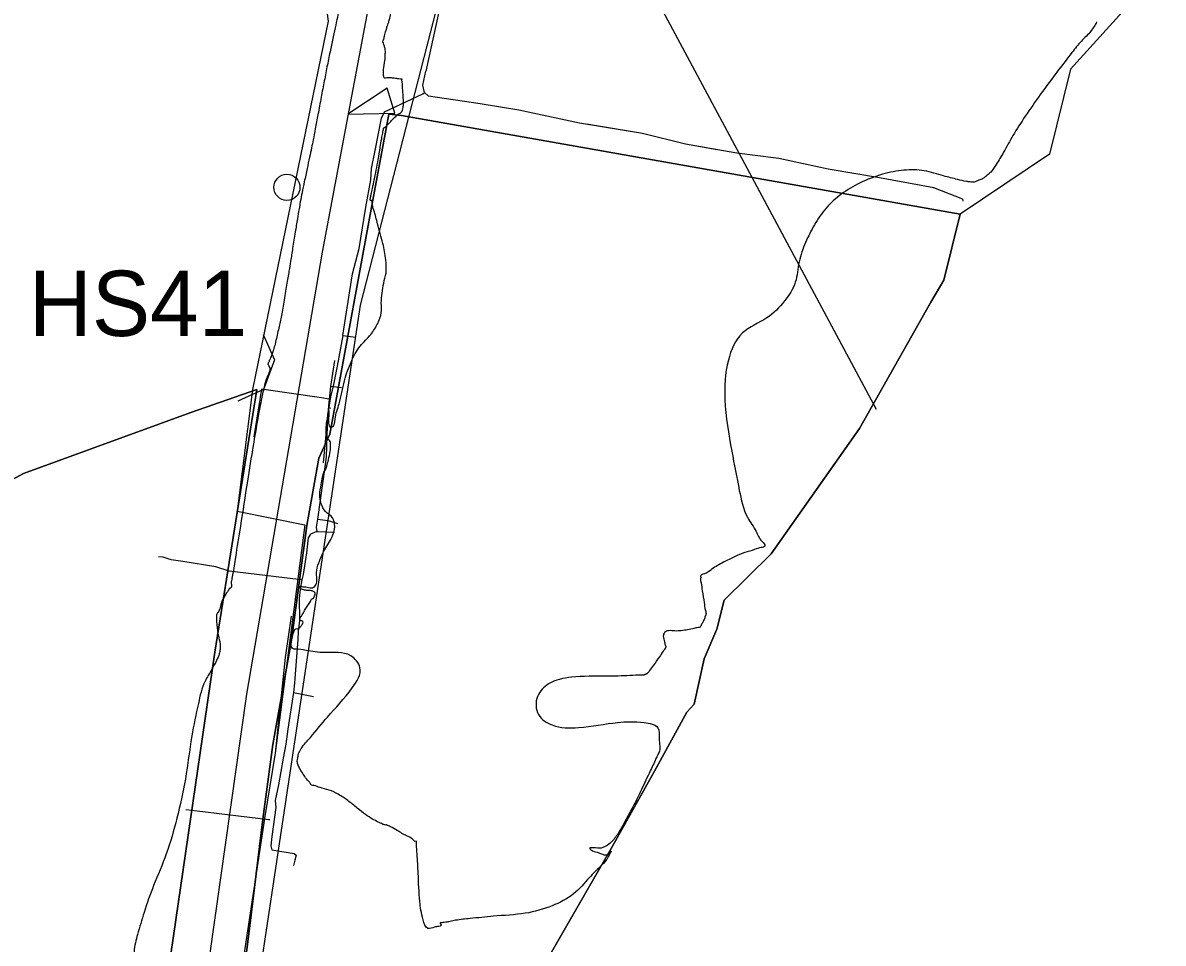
# Model space of a CAD drawing. Extents: x -478645 to -472650, y -1118147 to -1113892.
# Drawn here: x -475972.9 to -475798.3, y -1117585.1 to -1117444.2 of the extents above; entities that cross this region are included whole.
import ezdxf

# ---------------------------------------------------------------- set-up
doc = ezdxf.new("R2010")
doc.units = 0
for name, color, linetype in [('cesty', 7, 'Continuous'), ('el vedeni _VN', 7, 'Continuous'), ('hospodářské sjezdy', 7, 'Continuous'), ('ObPÚ', 7, 'Continuous'), ('plyn_stl', 7, 'Continuous'), ('silnice', 7, 'Continuous'), ('telekomunikační kabel_O2', 7, 'Continuous'), ('VAK_vodovod', 7, 'Continuous'), ('Vrstevnice_vedlejsi', 7, 'Continuous')]:
    doc.layers.add(name, color=color, linetype=linetype)

msp = doc.modelspace()

# ---------------------------------------------------------------- linework, layer by layer
at = {"layer": 'cesty'}
msp.add_line((-475915.938, -1117457.98), (-475917.133, -1117454.162), dxfattribs=at)
msp.add_lwpolyline([(-475917.133, -1117454.162), (-475923.164, -1117458.147), (-475915.938, -1117457.98)], dxfattribs=at)
msp.add_circle((-475932.467, -1117469.362), 2, dxfattribs=at)
at = {"layer": 'el vedeni _VN'}
msp.add_lwpolyline([(-475915.707, -1117366.222), (-475842.25, -1117503.35)], dxfattribs=at)
at = {"layer": 'hospodářské sjezdy'}
for p, q in [((-475936.094, -1117491.874), (-475934.346, -1117495.765)), ((-475934.346, -1117495.765), (-475936.078, -1117500.333)), ((-475936.078, -1117500.333), (-475939.967, -1117502.085))]:
    msp.add_line(p, q, dxfattribs=at)
at = {"layer": 'ObPÚ'}
for p, q in [((-475916.88, -1117458.16), (-475919.49, -1117472.13)), ((-475919.49, -1117472.13), (-475925.88, -1117507.14)), ((-475934.6, -1117554.69), (-475936.13, -1117566.09))]:
    msp.add_line(p, q, dxfattribs=at)
for points in [[(-475797.1, -1117434.24), (-475812.51, -1117451.24), (-475815.72, -1117464.29), (-475829.4, -1117473.48), (-475914.94, -1117458.35), (-475916.88, -1117458.16), (-475919.49, -1117472.13), (-475925.88, -1117507.14), (-475927.57, -1117510.84), (-475929.43, -1117521.14), (-475931.78, -1117538.72), (-475934.6, -1117554.69), (-475936.13, -1117566.09), (-475938.19, -1117582.83), (-475940.34, -1117599.73)], [(-475951.7, -1117685.1), (-475927.26, -1117688.72), (-475918.95, -1117689.8), (-475884.78, -1117695.44), (-475871.68, -1117697.52), (-475898.5, -1117669.12), (-475903.93, -1117664.35), (-475905.71, -1117629.13), (-475906.78, -1117612.16), (-475902.49, -1117604.75), (-475882.63, -1117570.25), (-475876.2, -1117558.77), (-475871.25, -1117549.71), (-475870.12, -1117548.49), (-475868.56, -1117541.56), (-475866.64, -1117537.01), (-475865.5, -1117532.56), (-475858.35, -1117525.46), (-475844.8, -1117506.28), (-475833.86, -1117486.94), (-475831.88, -1117483.59), (-475829.4, -1117473.48), (-475914.94, -1117458.35), (-475916.88, -1117458.16)], [(-475919.49, -1117472.13), (-475916.88, -1117458.16), (-475914.94, -1117458.35), (-475829.4, -1117473.48), (-475831.88, -1117483.59), (-475833.86, -1117486.94), (-475844.8, -1117506.28), (-475858.35, -1117525.46), (-475865.5, -1117532.56), (-475866.64, -1117537.01), (-475868.56, -1117541.56), (-475870.12, -1117548.49), (-475871.25, -1117549.71), (-475876.2, -1117558.77), (-475882.63, -1117570.25), (-475902.49, -1117604.75)], [(-475940.34, -1117599.73), (-475938.19, -1117582.83), (-475936.13, -1117566.09), (-475934.6, -1117554.69), (-475931.78, -1117538.72), (-475929.43, -1117521.14), (-475927.57, -1117510.84), (-475925.88, -1117507.14), (-475919.49, -1117472.13)], [(-475937.08, -1117500.29), (-475943.5, -1117540.53), (-475950.59, -1117589.22), (-475972.84, -1117590.29), (-476004.64, -1117592.26), (-475999.55, -1117575.26), (-475994.23, -1117573.44), (-475992.2, -1117563.25), (-475986.19, -1117534.11), (-475984.93, -1117525.82), (-475982.04, -1117518.19), (-475972.81, -1117513.2), (-475947.17, -1117503.84), (-475937.08, -1117500.29)], [(-475947.17, -1117503.84), (-475972.81, -1117513.2), (-475982.04, -1117518.19), (-475984.93, -1117525.82), (-475986.19, -1117534.11), (-475992.2, -1117563.25), (-475994.23, -1117573.44), (-475999.55, -1117575.26), (-476004.64, -1117592.26), (-475972.84, -1117590.29), (-475950.59, -1117589.22), (-475943.5, -1117540.53), (-475937.08, -1117500.29), (-475947.17, -1117503.84)], [(-475925.88, -1117507.14), (-475927.57, -1117510.84), (-475929.43, -1117521.14), (-475931.78, -1117538.72), (-475934.6, -1117554.69)], [(-475936.13, -1117566.09), (-475938.19, -1117582.83), (-475940.34, -1117599.73)]]:
    msp.add_lwpolyline(points, dxfattribs=at)
at = {"layer": 'plyn_stl'}
for p, q in [((-475925.98, -1117501.775), (-475926.943, -1117511.519)), ((-475947.94, -1117564.611), (-475946.213, -1117564.822)), ((-475946.213, -1117564.822), (-475935.234, -1117566.161)), ((-475935.234, -1117566.161), (-475935.062, -1117566.182))]:
    msp.add_line(p, q, dxfattribs=at)
for points in [[(-475925.179, -1117495.887), (-475925.776, -1117499.864), (-475925.98, -1117501.775), (-475927.156, -1117501.607), (-475936.338, -1117500.287), (-475937.535, -1117507.551)], [(-475924.115, -1117500.041), (-475924.12, -1117500.04), (-475924.5, -1117500), (-475925.776, -1117499.864)]]:
    msp.add_lwpolyline(points, dxfattribs=at)
at = {"layer": 'silnice'}
msp.add_lwpolyline([(-475957.898, -1117684.778), (-475949.882, -1117626.621), (-475938.626, -1117546.976), (-475927.029, -1117479.269), (-475917.649, -1117429.299), (-475903.982, -1117378.322)], dxfattribs=at)
at = {"layer": 'telekomunikační kabel_O2'}
for points in [[(-475967.4, -1117098.97), (-475940.43, -1117167.78), (-475950.06, -1117174), (-475931.33, -1117228.82), (-475924.1, -1117281.32), (-475911.23, -1117358.65), (-475927.92, -1117430.83), (-475926.17, -1117443.9), (-475937.75, -1117500.32), (-475940.1, -1117518.94), (-475929.72, -1117521.06), (-475934.27, -1117556.02), (-475935.89, -1117566.02), (-475936.969, -1117573.032)], [(-475891.45, -1117356.54), (-475891.64, -1117357.2), (-475890.45, -1117362.41), (-475889.23, -1117368.48), (-475890.21, -1117370.93), (-475900.63, -1117410.24), (-475907.44, -1117434.27), (-475911.21, -1117451.58)], [(-475911.41, -1117454.83), (-475911.67, -1117453.71), (-475911.21, -1117451.58)], [(-475923.91, -1117492.02), (-475922.43, -1117482.59), (-475921.39, -1117478.74), (-475920.39, -1117472.37), (-475919.64, -1117468.22), (-475919.5, -1117466.47), (-475918.95, -1117463.72), (-475918, -1117458.79), (-475917.51, -1117457.78), (-475911.68, -1117455.04), (-475911.41, -1117454.83)], [(-475866.596, -1117463.609), (-475871.46, -1117462.74), (-475878.05, -1117461.1), (-475887.67, -1117459.53), (-475896.96, -1117457.53), (-475902.86, -1117456.57), (-475910.78, -1117455.39), (-475911.41, -1117454.83)], [(-475857.14, -1117464.96), (-475863.57, -1117464.15), (-475871.46, -1117462.74), (-475878.05, -1117461.1), (-475886.596, -1117459.705)], [(-475828.923, -1117471.474), (-475828.99, -1117471.15), (-475833.42, -1117469.44), (-475841.75, -1117467.88), (-475849.62, -1117466.56), (-475857.14, -1117464.96)], [(-475923.91, -1117492.02), (-475924.79, -1117496.76), (-475925.31, -1117499.54), (-475925.81, -1117501.42), (-475926.04, -1117503.08)], [(-475923.91, -1117492.02), (-475921.9, -1117492.32)], [(-475926.04, -1117503.08), (-475926.26, -1117504.12), (-475926.26, -1117504.92), (-475926.36, -1117507.25), (-475926.48, -1117510.66), (-475926.65, -1117512.14), (-475927.78, -1117520.16)], [(-475926.04, -1117503.08), (-475925.78, -1117503.17)], [(-475927.78, -1117520.16), (-475927.97, -1117521.4), (-475927.89, -1117522.04)], [(-475927.78, -1117520.16), (-475926.14, -1117520.38), (-475924.73, -1117520.81)], [(-475927.89, -1117522.04), (-475928.86, -1117522.49), (-475929.19, -1117523.03), (-475929.45, -1117525.32), (-475929.97, -1117528.65), (-475930.16, -1117529.45)], [(-475927.89, -1117522.04), (-475925.19, -1117522.16)], [(-475930.16, -1117529.45), (-475931.57, -1117529.33), (-475941.31, -1117528.12), (-475943.33, -1117527.48), (-475948.39, -1117526.66), (-475950.2, -1117526.42), (-475951.4, -1117525.97), (-475952.12, -1117525.92)], [(-475930.16, -1117529.45), (-475930.43, -1117530.9), (-475930.6, -1117532.33), (-475930.55, -1117535.71), (-475930.75, -1117537.38), (-475930.78, -1117538.62), (-475931.26, -1117544.56), (-475931.29, -1117545.26), (-475931.44, -1117546.73)], [(-475931.82, -1117535.04), (-475932.74, -1117541.33), (-475934.27, -1117556.02), (-475935.89, -1117566.02), (-475937.71, -1117577.81), (-475938.91, -1117585.91), (-475941.61, -1117604.26), (-475944.33, -1117624.51)], [(-475931.44, -1117546.73), (-475932.33, -1117552.33), (-475932.65, -1117554.6), (-475933.06, -1117556.79), (-475933.78, -1117560.85), (-475934.28, -1117563.23), (-475934.17, -1117564.33), (-475934.76, -1117568.78), (-475934.91, -1117570.19), (-475934.8, -1117570.81), (-475931.38, -1117571.38), (-475931.07, -1117571.61), (-475931.27, -1117572.4), (-475931.48, -1117573.22)], [(-475931.44, -1117546.73), (-475928.4, -1117547.31)]]:
    msp.add_lwpolyline(points, dxfattribs=at)
at = {"layer": 'VAK_vodovod'}
msp.add_lwpolyline([(-475961.022, -1117076.006), (-475947.88, -1117107.78), (-475947.26, -1117108.989), (-475886.863, -1117255.251), (-475879.338, -1117287.714), (-475878.218, -1117296.341), (-475877.862, -1117316.562), (-475878.829, -1117320.819), (-475879.236, -1117324.31), (-475879.403, -1117324.54), (-475921.268, -1117487.378), (-475934.347, -1117574.649), (-475937.667, -1117596.666), (-475938.465, -1117600.746), (-475938.582, -1117601.233), (-475938.757, -1117601.897), (-475940.979, -1117601.583)], dxfattribs=at)
at = {"layer": 'Vrstevnice_vedlejsi'}
for points in [[(-475916.975, -1117444.292), (-475916.91, -1117444.15), (-475916.838, -1117443.929), (-475916.758, -1117443.629), (-475916.67, -1117443.25), (-475916.443, -1117442.153), (-475916.077, -1117440.337), (-475915.571, -1117437.802), (-475915.215, -1117436.045), (-475915.01, -1117435.066), (-475914.956, -1117434.864), (-475914.76, -1117434.04), (-475914.422, -1117432.594), (-475913.943, -1117430.524), (-475913.61, -1117429.082), (-475913.424, -1117428.266), (-475913.385, -1117428.077), (-475913.184, -1117427.193), (-475912.819, -1117425.614), (-475912.291, -1117423.339), (-475911.931, -1117421.787), (-475911.737, -1117420.958), (-475911.711, -1117420.852), (-475911.47, -1117419.881), (-475911.014, -1117418.045), (-475910.343, -1117415.344), (-475909.896, -1117413.541), (-475909.671, -1117412.636), (-475909.669, -1117412.628), (-475909.667, -1117412.619), (-475909.664, -1117412.607), (-475909.661, -1117412.594), (-475909.477, -1117411.965), (-475909.111, -1117410.721), (-475908.564, -1117408.862), (-475908.198, -1117407.614), (-475908.011, -1117406.977), (-475908.005, -1117406.952), (-475908, -1117406.932), (-475907.996, -1117406.917), (-475907.995, -1117406.907), (-475907.754, -1117405.931), (-475907.275, -1117403.988), (-475906.557, -1117401.079), (-475905.997, -1117398.788), (-475905.596, -1117397.117), (-475905.352, -1117396.064), (-475905.125, -1117395.027), (-475904.914, -1117394.006), (-475904.721, -1117393.002), (-475904.431, -1117391.559), (-475904.045, -1117389.677), (-475903.563, -1117387.357), (-475903.25, -1117385.773), (-475903.106, -1117384.926), (-475903.131, -1117384.815), (-475903.261, -1117384.756), (-475903.497, -1117384.749), (-475903.839, -1117384.794), (-475904.936, -1117385.955), (-475906.789, -1117388.231), (-475909.397, -1117391.622), (-475911.147, -1117393.894), (-475912.039, -1117395.047), (-475912.072, -1117395.08), (-475912.108, -1117395.141), (-475912.145, -1117395.227), (-475912.185, -1117395.34), (-475912.276, -1117395.491), (-475912.417, -1117395.68), (-475912.611, -1117395.908), (-475913.012, -1117397.232), (-475913.622, -1117399.653), (-475914.441, -1117403.172), (-475915.248, -1117406.458), (-475916.043, -1117409.512), (-475916.828, -1117412.333), (-475917.46, -1117414.614), (-475917.94, -1117416.353), (-475918.268, -1117417.552), (-475918.666, -1117419.012), (-475919.134, -1117420.732), (-475919.673, -1117422.713), (-475920.196, -1117424.706), (-475920.704, -1117426.711), (-475921.195, -1117428.727), (-475921.645, -1117430.593), (-475922.054, -1117432.306), (-475922.421, -1117433.869), (-475922.836, -1117435.571), (-475923.299, -1117437.415), (-475923.809, -1117439.399), (-475924.263, -1117441.241), (-475924.661, -1117442.942), (-475925.002, -1117444.501), (-475925.384, -1117446.3), (-475925.807, -1117448.34)], [(-475926.806, -1117512.989), (-475926.594, -1117512.679), (-475926.364, -1117512.04), (-475926.115, -1117511.073), (-475925.848, -1117509.779), (-475925.79, -1117508.798), (-475925.942, -1117508.13), (-475926.304, -1117507.777), (-475926.467, -1117507.007), (-475926.43, -1117505.822), (-475926.193, -1117504.22), (-475926.061, -1117503.535), (-475926.032, -1117503.767), (-475926.107, -1117504.915), (-475926.054, -1117505.677), (-475925.872, -1117506.054), (-475925.562, -1117506.044), (-475925.091, -1117504.861), (-475924.459, -1117502.506), (-475923.667, -1117498.977), (-475922.599, -1117496.031), (-475921.256, -1117493.667), (-475919.639, -1117491.885), (-475918.56, -1117490.191), (-475918.018, -1117488.587), (-475918.015, -1117487.071), (-475917.893, -1117485.547), (-475917.653, -1117484.016), (-475917.295, -1117482.477), (-475917.333, -1117480.451), (-475917.767, -1117477.938), (-475918.596, -1117474.938), (-475919.15, -1117472.871), (-475919.428, -1117471.736), (-475919.431, -1117471.534), (-475919.47, -1117471.408), (-475919.543, -1117471.356), (-475919.652, -1117471.379), (-475919.714, -1117471.331), (-475919.728, -1117471.212), (-475919.695, -1117471.021), (-475919.578, -1117470.457), (-475919.377, -1117469.521), (-475919.091, -1117468.211), (-475918.797, -1117466.73), (-475918.495, -1117465.079), (-475918.184, -1117463.257), (-475917.954, -1117461.912), (-475917.804, -1117461.044), (-475917.736, -1117460.653), (-475917.673, -1117460.385), (-475917.615, -1117460.241), (-475917.563, -1117460.221), (-475917.503, -1117460.188), (-475917.434, -1117460.142), (-475917.357, -1117460.084), (-475917.117, -1117459.844), (-475916.715, -1117459.423), (-475916.15, -1117458.821), (-475915.694, -1117458.384), (-475915.347, -1117458.112), (-475915.11, -1117458.006), (-475914.917, -1117457.811), (-475914.77, -1117457.525), (-475914.668, -1117457.15), (-475914.632, -1117456.464), (-475914.662, -1117455.467), (-475914.757, -1117454.161), (-475914.82, -1117453.286), (-475914.849, -1117452.843), (-475914.845, -1117452.831), (-475914.844, -1117452.821), (-475914.845, -1117452.811), (-475914.848, -1117452.803), (-475914.854, -1117452.799), (-475914.862, -1117452.799), (-475914.872, -1117452.802), (-475915.096, -1117452.775), (-475915.535, -1117452.719), (-475916.188, -1117452.632), (-475916.735, -1117452.594), (-475917.175, -1117452.603), (-475917.509, -1117452.66), (-475917.671, -1117452.239), (-475917.659, -1117451.338), (-475917.476, -1117449.959), (-475917.402, -1117448.881), (-475917.44, -1117448.105), (-475917.587, -1117447.631), (-475917.691, -1117447.306), (-475917.752, -1117447.131), (-475917.769, -1117447.105), (-475917.697, -1117446.794), (-475917.537, -1117446.198), (-475917.288, -1117445.316), (-475917.101, -1117444.68), (-475916.975, -1117444.292)], [(-475808.497, -1117444.035), (-475808.88, -1117444.729), (-475809.396, -1117445.448), (-475810.046, -1117446.192), (-475810.829, -1117446.96), (-475812.268, -1117448.71), (-475814.364, -1117451.44), (-475817.116, -1117455.152), (-475819.429, -1117458.48), (-475821.301, -1117461.425), (-475822.733, -1117463.986), (-475823.869, -1117465.856), (-475824.71, -1117467.033), (-475825.256, -1117467.518), (-475825.714, -1117467.878), (-475826.086, -1117468.115), (-475826.372, -1117468.227), (-475826.636, -1117468.331), (-475826.88, -1117468.427), (-475827.102, -1117468.514), (-475827.434, -1117468.549), (-475827.875, -1117468.533), (-475828.425, -1117468.465), (-475829.777, -1117468.158), (-475831.929, -1117467.611), (-475834.883, -1117466.824), (-475837.998, -1117466.742), (-475841.274, -1117467.362), (-475844.71, -1117468.687), (-475847.59, -1117470.415), (-475849.915, -1117472.545), (-475851.683, -1117475.078), (-475853.059, -1117477.814), (-475854.041, -1117480.752), (-475854.63, -1117483.892), (-475856.275, -1117486.757), (-475858.974, -1117489.346), (-475862.729, -1117491.66), (-475864.878, -1117495.835), (-475865.419, -1117501.869), (-475864.354, -1117509.765), (-475863.199, -1117515.764), (-475861.956, -1117519.867), (-475860.624, -1117522.073), (-475859.743, -1117523.554), (-475859.312, -1117524.308), (-475859.332, -1117524.337), (-475859.846, -1117524.509), (-475860.853, -1117524.824), (-475862.354, -1117525.281), (-475863.943, -1117525.933), (-475865.62, -1117526.779), (-475867.386, -1117527.82), (-475868.557, -1117528.532), (-475869.131, -1117528.918), (-475869.11, -1117528.976), (-475869.104, -1117529.054), (-475869.115, -1117529.153), (-475869.141, -1117529.272), (-475869.061, -1117529.943), (-475868.875, -1117531.166), (-475868.582, -1117532.941), (-475868.393, -1117534.142), (-475868.307, -1117534.77), (-475868.324, -1117534.824), (-475868.346, -1117534.875), (-475868.373, -1117534.923), (-475868.404, -1117534.968), (-475868.435, -1117535.044), (-475868.464, -1117535.15), (-475868.491, -1117535.288), (-475868.585, -1117535.521), (-475868.744, -1117535.849), (-475868.969, -1117536.272), (-475869.119, -1117536.555), (-475869.195, -1117536.699), (-475869.197, -1117536.704), (-475869.518, -1117536.776), (-475870.159, -1117536.915), (-475871.12, -1117537.121), (-475872.088, -1117537.246), (-475873.063, -1117537.289), (-475874.046, -1117537.25), (-475874.637, -1117537.514), (-475874.836, -1117538.082), (-475874.643, -1117538.952), (-475874.526, -1117539.55), (-475874.485, -1117539.876), (-475874.521, -1117539.93), (-475874.841, -1117540.388), (-475875.446, -1117541.248), (-475876.337, -1117542.511), (-475876.953, -1117543.366), (-475877.296, -1117543.813), (-475877.366, -1117543.852), (-475877.441, -1117543.89), (-475877.52, -1117543.926)], [(-475925.807, -1117448.34), (-475926.271, -1117450.621), (-475926.743, -1117453.028), (-475927.223, -1117455.562), (-475927.71, -1117458.222), (-475928.119, -1117460.397), (-475928.448, -1117462.085), (-475928.698, -1117463.287), (-475929.008, -1117464.755), (-475929.377, -1117466.489), (-475929.805, -1117468.489), (-475930.153, -1117470.183), (-475930.42, -1117471.572), (-475930.607, -1117472.656), (-475930.864, -1117474.203), (-475931.192, -1117476.212), (-475931.591, -1117478.685), (-475931.911, -1117480.673), (-475932.154, -1117482.178), (-475932.319, -1117483.199), (-475932.507, -1117484.336), (-475932.716, -1117485.589), (-475932.947, -1117486.958), (-475933.165, -1117488.181), (-475933.369, -1117489.257), (-475933.56, -1117490.186), (-475933.776, -1117491.179), (-475934.018, -1117492.236), (-475934.284, -1117493.357), (-475934.519, -1117494.236), (-475934.723, -1117494.873), (-475934.895, -1117495.268), (-475935.041, -1117495.607), (-475935.161, -1117495.889), (-475935.254, -1117496.115), (-475935.322, -1117496.274), (-475935.366, -1117496.367), (-475935.386, -1117496.394), (-475935.348, -1117496.507), (-475935.253, -1117496.706), (-475935.101, -1117496.991), (-475935.105, -1117497.404), (-475935.264, -1117497.944), (-475935.579, -1117498.612), (-475935.962, -1117499.972), (-475936.413, -1117502.024), (-475936.932, -1117504.768), (-475937.635, -1117508.885), (-475938.521, -1117514.375), (-475939.592, -1117521.239), (-475940.344, -1117525.997), (-475940.776, -1117528.651), (-475940.89, -1117529.2), (-475940.962, -1117529.609), (-475940.994, -1117529.877), (-475940.984, -1117530.005), (-475940.975, -1117530.143), (-475940.967, -1117530.29), (-475940.96, -1117530.446), (-475940.993, -1117530.576), (-475941.066, -1117530.679), (-475941.18, -1117530.754), (-475941.378, -1117530.99), (-475941.658, -1117531.386), (-475942.021, -1117531.943), (-475942.311, -1117532.508), (-475942.528, -1117533.081), (-475942.672, -1117533.663), (-475942.827, -1117534.113), (-475942.993, -1117534.43), (-475943.171, -1117534.615), (-475943.259, -1117535.054), (-475943.258, -1117535.746), (-475943.166, -1117536.692), (-475943.05, -1117537.531), (-475942.909, -1117538.261), (-475942.742, -1117538.884), (-475942.673, -1117539.509), (-475942.701, -1117540.138), (-475942.826, -1117540.769), (-475943.252, -1117541.788), (-475943.979, -1117543.194), (-475945.007, -1117544.986), (-475946.021, -1117548.378), (-475947.023, -1117553.369), (-475948.011, -1117559.959), (-475949.315, -1117565.973), (-475950.935, -1117571.413), (-475952.871, -1117576.278), (-475954.339, -1117580.395), (-475955.339, -1117583.764), (-475955.87, -1117586.385), (-475955.761, -1117588.893), (-475955.011, -1117591.286), (-475953.62, -1117593.565), (-475952.783, -1117595.731), (-475952.5, -1117597.782)], [(-475917.209, -1117566.997), (-475917.413, -1117566.999), (-475917.838, -1117566.85), (-475918.484, -1117566.55), (-475919.352, -1117566.1), (-475920.421, -1117565.397), (-475921.69, -1117564.443), (-475923.161, -1117563.237), (-475924.603, -1117562.304), (-475926.015, -1117561.646), (-475927.397, -1117561.261), (-475928.341, -1117560.961), (-475928.845, -1117560.747), (-475928.911, -1117560.617), (-475929.032, -1117560.447), (-475929.209, -1117560.235), (-475929.442, -1117559.984), (-475929.74, -1117559.574), (-475930.103, -1117559.008), (-475930.53, -1117558.283), (-475930.791, -1117557.665), (-475930.885, -1117557.153), (-475930.813, -1117556.748), (-475930.761, -1117556.441), (-475930.728, -1117556.235), (-475930.715, -1117556.128), (-475930.636, -1117555.937), (-475930.491, -1117555.662), (-475930.279, -1117555.304), (-475928.872, -1117553.578), (-475926.271, -1117550.484), (-475922.475, -1117546.022), (-475921.285, -1117542.888), (-475922.703, -1117541.08), (-475926.727, -1117540.6), (-475929.539, -1117540.262), (-475931.141, -1117540.067), (-475931.531, -1117540.015), (-475931.757, -1117539.753), (-475931.82, -1117539.281), (-475931.719, -1117538.6), (-475931.605, -1117538.034), (-475931.479, -1117537.582), (-475931.34, -1117537.244), (-475931.183, -1117537.027), (-475931.008, -1117536.932), (-475930.816, -1117536.958), (-475930.6, -1117536.85), (-475930.362, -1117536.608), (-475930.1, -1117536.232), (-475930.002, -1117535.958), (-475930.069, -1117535.784), (-475930.299, -1117535.712), (-475930.449, -1117535.66), (-475930.518, -1117535.629), (-475930.507, -1117535.619), (-475930.497, -1117535.589), (-475930.488, -1117535.539), (-475930.48, -1117535.469), (-475930.458, -1117535.388), (-475930.42, -1117535.296), (-475930.366, -1117535.192), (-475930.143, -1117534.813), (-475929.751, -1117534.159), (-475929.188, -1117533.23), (-475928.781, -1117532.611), (-475928.528, -1117532.302), (-475928.43, -1117532.303), (-475928.33, -1117532.18), (-475928.228, -1117531.932), (-475928.124, -1117531.56), (-475928.283, -1117531.293), (-475928.707, -1117531.132), (-475929.394, -1117531.077), (-475929.9, -1117530.997), (-475930.223, -1117530.891), (-475930.365, -1117530.76), (-475930.455, -1117530.646), (-475930.495, -1117530.551), (-475930.484, -1117530.473), (-475930.182, -1117530.473), (-475929.588, -1117530.55), (-475928.702, -1117530.705), (-475928.133, -1117530.394), (-475927.88, -1117529.619), (-475927.943, -1117528.378), (-475927.584, -1117526.86), (-475926.801, -1117525.067), (-475925.595, -1117522.997), (-475925.153, -1117521.293), (-475925.474, -1117519.954), (-475926.559, -1117518.981), (-475927.212, -1117517.81), (-475927.435, -1117516.439), (-475927.226, -1117514.869), (-475927.016, -1117513.719), (-475926.806, -1117512.989)], [(-475877.52, -1117543.926), (-475877.604, -1117543.962), (-475877.689, -1117543.993), (-475877.775, -1117544.021), (-475877.862, -1117544.045), (-475877.948, -1117544.06), (-475878.032, -1117544.067), (-475878.116, -1117544.066), (-475879.954, -1117544.117), (-475883.546, -1117544.221), (-475888.893, -1117544.379), (-475892.41, -1117545.409), (-475894.095, -1117547.313), (-475893.949, -1117550.091), (-475891.857, -1117551.681), (-475887.82, -1117552.084), (-475881.837, -1117551.3), (-475877.783, -1117551.317), (-475875.659, -1117552.136), (-475875.464, -1117553.757), (-475875.382, -1117554.938), (-475875.411, -1117555.68), (-475875.552, -1117555.983), (-475876.087, -1117557.12), (-475877.015, -1117559.091), (-475878.337, -1117561.896), (-475879.605, -1117564.421), (-475880.82, -1117566.665), (-475881.983, -1117568.628), (-475883.168, -1117569.918), (-475884.374, -1117570.535), (-475885.603, -1117570.478), (-475886.113, -1117570.566), (-475885.904, -1117570.799), (-475884.976, -1117571.176), (-475884.277, -1117571.434), (-475883.805, -1117571.571), (-475883.562, -1117571.589), (-475883.372, -1117571.546), (-475883.234, -1117571.443), (-475883.148, -1117571.279), (-475883.059, -1117571.152), (-475882.964, -1117571.062), (-475882.866, -1117571.008), (-475882.827, -1117571.02), (-475882.848, -1117571.098), (-475882.928, -1117571.243), (-475883.026, -1117571.423), (-475883.14, -1117571.64), (-475883.272, -1117571.892), (-475883.39, -1117572.103), (-475883.494, -1117572.274), (-475883.585, -1117572.403), (-475884.466, -1117573.326), (-475886.138, -1117575.043), (-475888.6, -1117577.554), (-475891.876, -1117579.379), (-475895.966, -1117580.517), (-475900.871, -1117580.97), (-475904.427, -1117581.33), (-475906.634, -1117581.598), (-475907.493, -1117581.773), (-475908.147, -1117581.892), (-475908.598, -1117581.955), (-475908.845, -1117581.962), (-475908.983, -1117581.997), (-475909.013, -1117582.058), (-475908.934, -1117582.146), (-475908.886, -1117582.234), (-475908.872, -1117582.322), (-475908.889, -1117582.41), (-475909.23, -1117582.525), (-475909.895, -1117582.666), (-475910.884, -1117582.832), (-475911.626, -1117581.508), (-475912.121, -1117578.693), (-475912.369, -1117574.387), (-475912.536, -1117571.461), (-475912.622, -1117569.913), (-475912.626, -1117569.745), (-475912.628, -1117569.633), (-475912.629, -1117569.575), (-475912.628, -1117569.572), (-475912.626, -1117569.565), (-475912.623, -1117569.554), (-475912.62, -1117569.537), (-475912.626, -1117569.523), (-475912.64, -1117569.51), (-475912.664, -1117569.498), (-475912.681, -1117569.492), (-475912.691, -1117569.49), (-475912.695, -1117569.493), (-475913.176, -1117569.217), (-475914.134, -1117568.663), (-475915.57, -1117567.829), (-475916.595, -1117567.274), (-475917.209, -1117566.997)]]:
    msp.add_spline(points, degree=3, dxfattribs=at)

# ---------------------------------------------------------------- texts
at = {"layer": 'hospodářské sjezdy'}
msp.add_text('HS41', height=10, rotation=359.99999, dxfattribs=at).set_placement((-475971.988, -1117492.122))

doc.saveas('drawing.dxf')
